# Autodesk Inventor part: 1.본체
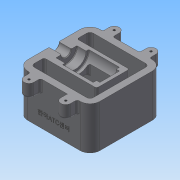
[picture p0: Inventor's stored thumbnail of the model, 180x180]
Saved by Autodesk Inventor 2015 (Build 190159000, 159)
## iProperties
Created: 2018-01
Part Number: 1.본체
Material: 일반
Document SubType Name: Modeling
Designer: user
Density: 1 g/cm^3
Appearance: 기본값
Author: user
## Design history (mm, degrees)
sketch "스케치1"
  geometry: L1 (-55, -55)-(55, -55); L2 (55, -55)-(55, 55); L3 (55, 55)-(-55, 55); L4 (-55, 55)-(-55, -55); L5 (-55, -55)-(55, 55); L6 (55, -55)-(-55, 55); 1 further point
  constraints: 12 end point, 2 midpoint, 2 parallel, 1 horizontal, 1 perpendicular
  dimensions: "d0" = 110 distance of L1.end L2.end; "d1" = 110 distance of L2.end L3.end
extrude "돌출1" new body sketch "스케치1" stored distance "d2" = 65; taper "d3" = 0 deg
fillet "모깎기1" dims "d4" = 15
sketch "스케치13" dims "d0" = 110, "d1" = 110
  geometry: L1 (80, -65)-(0, -65) reference; L2 (95, -65)-(95, 0) reference; 2 further points
  constraints: 1 other
  dimensions: "d79" = 55 distance from line of L2 point (40, -45); "d80" = 20 distance from line of L1 point (40, -45)
feature "엠보싱1" sketch "스케치13" dims "d0" = 110, "d1" = 110, "d5" = 10, "d6" = 10, "d7" = 5, "d81" = 0.5, "d82" = 0
sketch "스케치2"
  geometry: L1 (40, 55)-(-40, 55) reference; L2 (-55, 40)-(-55, -40) reference; L3 (40, -45)-(-40, -45); L4 (-45, -40)-(-45, 40); L5 (-40, 45)-(40, 45); L6 (45, 40)-(45, -40); L7 (45, -45)-(-45, 45); L8 (-45, -45)-(45, 45); A1 r 5 centre (-40, 40) between (-40, 45) and (-45, 40); A2 r 5 centre (40, 40) between (45, 40) and (40, 45); A3 r 5 centre (40, -40) between (40, -45) and (45, -40); A4 r 5 centre (-40, -40) between (-45, -40) and (-40, -45); 1 further point
  constraints: 12 end point, 8 point on circle, 8 point on line, 8 tangent, 4 centre point, 3 equal radius, 2 midpoint, 2 parallel, 1 horizontal, 1 perpendicular
  dimensions: "d5" = 10 distance between parallel lines of L2 L4; "d6" = 10 distance between parallel lines of L1 L5; "d7" = 5 radius of A1
extrude "돌출2" cut sketch "스케치2" distance "d8" = 65; taper "d9" = 0 deg
sketch "스케치3"
  geometry: L1 (-55, 40)-(-55, -40) reference; L2 (-40, -55)-(40, -55) reference; L3 (-28, -65)-(28, -65); L4 (-20.5, -65)-(-20.5, -55); L5 (-35.5, -65)-(-35.5, -55); A1 r 7.5 centre (-28, -65) between (-35.5, -65) and (-20.5, -65); 1 further point
  constraints: 6 end point, 3 point on line, 2 perpendicular, 2 point on circle, 2 tangent, 1 centre point, 1 coincident, 1 horizontal
  dimensions: "d11" = 56 distance of L3.start L3.end; "d12" = 27 distance from line of L1 L3.start; "d13" = 10 distance between parallel lines of L3 L2; "d15" = 7.5 radius of A1
extrude "돌출3" join sketch "스케치3" distance "d16" = 20; taper "d17" = 0 deg
sketch "스케치4"
  geometry: L1 (55, -32.5)-(40, -32.5) reference; L2 (45, 32.5)-(45, -32.5) reference; L3 (45, -23.936)-(-35, -2.5); L4 (-55, 32.5)-(-55, -32.5) reference; L5 (40, 32.5)-(-40, 32.5) reference; L6 (-35, -2.5)-(-35, 32.5); L7 (45, 32.5)-(-35, 32.5); L8 (45, 32.5)-(45, -23.936); 1 further point
  constraints: 8 end point, 2 perpendicular, 2 point on line, 1 collinear
  dimensions: "d18" = 105 deg angle of L2 L3; "d19" = 20 distance from line of L4 L3.end; "d20" = 30 vertical distance of L4.end L3.end
extrude "돌출4" join sketch "스케치4" stored distance "d21" = 50; taper "d22" = 0 deg
sketch "스케치5"
  geometry: L1 (55, -32.5)-(55, 32.5) reference; L2 (55, 32.5)-(-30, 32.5); L3 (45, 32.5)-(-35, 32.5) reference; L4 (55, 32.5)-(55, 40); L5 (55, 40)-(36, 40); L6 (36, 40)-(36, 47.5); L7 (35, 48.5)-(22, 48.5); L8 (22, 48.5)-(22, 51.5); L9 (21, 52.5)-(-24, 52.5); L10 (-25, 51.5)-(-25, 47.5); L11 (-25, 47.5)-(-29, 47.5); L12 (-30, 46.5)-(-30, 32.5); A1 r 1 centre (-29, 46.5) between (-29, 47.5) and (-30, 46.5); A2 r 1 centre (-24, 51.5) between (-24, 52.5) and (-25, 51.5); A3 r 1 centre (21, 51.5) between (22, 51.5) and (21, 52.5); A4 r 1 centre (35, 47.5) between (36, 47.5) and (35, 48.5); 5 further points
  constraints: 20 end point, 9 point on line, 8 point on circle, 8 tangent, 4 centre point, 4 vertical, 3 equal radius, 2 perpendicular, 1 horizontal, 1 parallel
  dimensions: "d24" = 15 diameter of L5 L2; "d25" = 32 diameter of L7 L2; "d26" = 40 diameter of L9 L2; "d28" = 30 diameter of L11 L2; "d29" = 19 distance of L4.end L5.end; "d30" = 14 distance of point (36, 48.5) L7.end; "d31" = 47 distance of point (22, 52.5) point (-25, 52.5); "d32" = 5 distance of L10.end point (-30, 47.5); "d33" = 1 radius of A1
revolve "회전1" sketch "스케치5" stored, may be unused: angle "d34" = 90 deg
sketch "스케치8"
  geometry: L1 (55, -21.439)-(-20, -1.343); L2 (-35, -2.5)-(45, -23.936) reference; L3 (21, 12.5)-(-24, 12.5) reference; L4 (17, 26.343)-(-20, 26.343); L5 (-20, 26.343)-(-20, -1.343); L6 (17, 6.743)-(17, 26.343); L7 (17, 26.343)-(-20, -1.343); L8 (-20, 26.343)-(17, -1.343); L9 (55, -32.5)-(55, 32.5) reference; L10 (55, -3.439)-(17, 6.743); 2 further points
  constraints: 14 end point, 3 midpoint, 3 parallel, 2 point on line, 1 horizontal, 1 perpendicular
  dimensions: "d40" = 5 distance between parallel lines of L2 L1; "d42" = 37 distance of L4.start L4.end; "d48" = 27.68571 distance of L4.end L1.end; "d83" = 18 distance of L1.start L10.start
extrude "돌출5" cut sketch "스케치8" stored distance "d50" = 30; taper "d51" = 0 deg
sketch "스케치9"
  geometry: A1 r 7.5 centre (-28, -65) between (-35.5, -65) and (-20.5, -65) reference; A2 r 7.5 centre (28, -65) between (20.5, -65) and (35.5, -65) reference; A3 r 7.5 centre (28, 65) between (35.5, 65) and (20.5, 65) reference; A4 r 7.5 centre (-28, 65) between (-20.5, 65) and (-35.5, 65) reference; 5 further points
  constraints: 4 coincident
hole "구멍1" sketch "스케치9" at (-28, -65), (28, -65), (28, 65), (-28, 65) diameter "d52" = 3.242; stored, may be unused: countersink angle "d56" = 90 deg, drill point angle "d58" = 118 deg; dims "d53" = 9, "d54" = 4, "d55" = 2, "d57" = 11
fillet "모깎기2" dims "d59" = 3
fillet "모깎기3" dims "d60" = 3
fillet "모깎기4" dims "d61" = 3
fillet "모깎기5" dims "d62" = 3
fillet "모깎기6" dims "d63" = 3
fillet "모깎기7" dims "d64" = 3
chamfer "모따기1" distance "d65" = 1; stored, may be unused: second distance "d66" = 2, angle "d67" = 45 deg
chamfer "모따기2" distance "d76" = 1; stored, may be unused: second distance "d77" = 2, angle "d78" = 45 deg
node "솔리드1"
mirror "대칭1"
mirror "대칭2"
